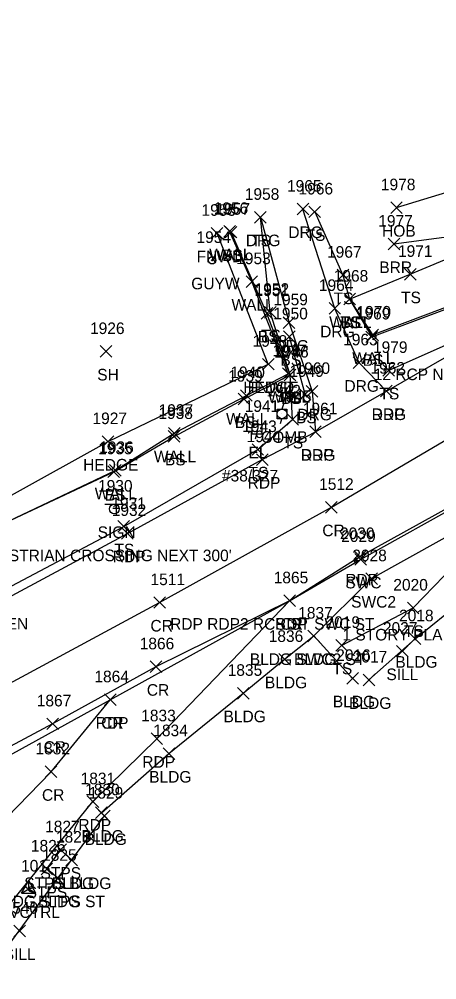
# Model space of a CAD drawing. Extents: x 1657482 to 1661439, y 647981 to 649041.
# Drawn here: x 1660007.4 to 1660079.4, y 648093.2 to 648258.8 of the extents above; entities that cross this region are included whole.
import ezdxf

# ---------------------------------------------------------------- set-up
doc = ezdxf.new("R2010")
doc.units = 0
for name, color, linetype in [('C_A', 7, 'Continuous'), ('C_I', 7, 'Continuous'), ('CPSM', 7, 'Continuous'), ('D_C', 7, 'Continuous'), ('L_A', 7, 'Continuous'), ('L_C', 7, 'Continuous'), ('L_I', 7, 'Continuous'), ('L_TIC', 7, 'Continuous'), ('LABL', 7, 'Continuous'), ('LAHR', 7, 'Continuous'), ('LBC', 7, 'Continuous'), ('LBF', 7, 'Continuous'), ('LELB', 7, 'Continuous'), ('LFNC', 7, 'Continuous'), ('LW', 7, 'Continuous'), ('P_A', 7, 'Continuous'), ('P_I', 7, 'Continuous'), ('P_TIC', 7, 'Continuous'), ('PET', 7, 'Continuous'), ('PRC', 7, 'Continuous'), ('R_A', 7, 'Continuous'), ('R_C', 7, 'Continuous'), ('R_I', 7, 'Continuous'), ('R_TIC', 7, 'Continuous'), ('RDG', 7, 'Continuous'), ('RSW', 7, 'Continuous'), ('S_A', 7, 'Continuous'), ('S_C', 7, 'Continuous'), ('S_I', 7, 'Continuous'), ('SSGN', 7, 'Continuous'), ('U_A', 7, 'Continuous'), ('U_C', 7, 'Continuous'), ('U_I', 7, 'Continuous'), ('UEPT', 7, 'Continuous'), ('UP', 7, 'Continuous'), ('UPGW', 7, 'Continuous')]:
    doc.layers.add(name, color=color, linetype=linetype)

msp = doc.modelspace()

# ---------------------------------------------------------------- linework, layer by layer
at = {"layer": 'CPSM'}
for p, q in [((1660007.81, 648108.16), (1660009.06, 648110.32)), ((1660007.81, 648108.16), (1660009.06, 648108.88)), ((1660010.31, 648108.16), (1660009.06, 648110.32)), ((1660009.06, 648108.88), (1660009.06, 648110.32)), ((1660009.06, 648108.88), (1660009.06, 648108.88)), ((1660009.06, 648108.88), (1660010.31, 648108.16)), ((1660007.81, 648108.16), (1660010.31, 648108.16))]:
    msp.add_line(p, q, dxfattribs=at)
at = {"layer": 'L_TIC'}
for points in [[(1660057.36, 648224.62), (1660059.36, 648226.62)], [(1660059.36, 648224.62), (1660057.36, 648226.62)], [(1660071.44, 648225.34), (1660073.44, 648227.34)], [(1660073.44, 648225.34), (1660071.44, 648227.34)], [(1660047.99, 648223.69), (1660049.99, 648225.69)], [(1660049.99, 648223.69), (1660047.99, 648225.69)], [(1660042.69, 648221.26), (1660044.69, 648223.26)], [(1660044.69, 648221.26), (1660042.69, 648223.26)], [(1660042.94, 648221.12), (1660044.94, 648223.12)], [(1660044.94, 648221.12), (1660042.94, 648223.12)], [(1660040.53, 648220.94), (1660042.53, 648222.94)], [(1660042.53, 648220.94), (1660040.53, 648222.94)], [(1660070.99, 648219.06), (1660072.99, 648221.06)], [(1660072.99, 648219.06), (1660070.99, 648221.06)], [(1660062.21, 648213.71), (1660064.21, 648215.71)], [(1660064.21, 648213.71), (1660062.21, 648215.71)], [(1660073.82, 648213.86), (1660075.82, 648215.86)], [(1660075.82, 648213.86), (1660073.82, 648215.86)], [(1660046.51, 648212.6), (1660048.51, 648214.6)], [(1660048.51, 648212.6), (1660046.51, 648214.6)], [(1660063.36, 648209.58), (1660065.36, 648211.58)], [(1660065.36, 648209.58), (1660063.36, 648211.58)], [(1660063.36, 648209.58), (1660065.36, 648211.58)], [(1660065.36, 648209.58), (1660063.36, 648211.58)], [(1660063.36, 648209.58), (1660065.36, 648211.58)], [(1660065.36, 648209.58), (1660063.36, 648211.58)], [(1660049.11, 648207.1), (1660051.11, 648209.1)], [(1660051.11, 648207.1), (1660049.11, 648209.1)], [(1660049.68, 648207.31), (1660051.68, 648209.31)], [(1660051.68, 648207.31), (1660049.68, 648209.31)], [(1660052.99, 648203.08), (1660054.99, 648205.08)], [(1660054.99, 648203.08), (1660052.99, 648205.08)], [(1660067.18, 648203.07), (1660069.18, 648205.07)], [(1660069.18, 648203.07), (1660067.18, 648205.07)], [(1660067.33, 648203.39), (1660069.33, 648205.39)], [(1660069.33, 648203.39), (1660067.33, 648205.39)], [(1660021.38, 648200.55), (1660023.38, 648202.55)], [(1660023.38, 648200.55), (1660021.38, 648202.55)], [(1660049.35, 648198.36), (1660051.35, 648200.36)], [(1660051.35, 648198.36), (1660049.35, 648200.36)], [(1660049.35, 648198.36), (1660051.35, 648200.36)], [(1660051.35, 648198.36), (1660049.35, 648200.36)], [(1660052.79, 648196.7), (1660054.79, 648198.7)], [(1660054.79, 648196.7), (1660052.79, 648198.7)], [(1660053.1, 648196.5), (1660055.1, 648198.5)], [(1660055.1, 648196.5), (1660053.1, 648198.5)], [(1660053.1, 648196.5), (1660055.1, 648198.5)], [(1660055.1, 648196.5), (1660053.1, 648198.5)], [(1660070.09, 648197.29), (1660072.09, 648199.29)], [(1660072.09, 648197.29), (1660070.09, 648199.29)], [(1660045.58, 648192.95), (1660047.58, 648194.95)], [(1660047.58, 648192.95), (1660045.58, 648194.95)], [(1660055.68, 648193.17), (1660057.68, 648195.17)], [(1660057.68, 648193.17), (1660055.68, 648195.17)], [(1660045.14, 648192.34), (1660047.14, 648194.34)], [(1660047.14, 648192.34), (1660045.14, 648194.34)], [(1660053.53, 648188.83), (1660055.53, 648190.83)], [(1660055.53, 648188.83), (1660053.53, 648190.83)], [(1660033.14, 648186.45), (1660035.14, 648188.45)], [(1660035.14, 648186.45), (1660033.14, 648188.45)], [(1660021.75, 648185.02), (1660023.75, 648187.02)], [(1660023.75, 648185.02), (1660021.75, 648187.02)], [(1660033.1, 648185.91), (1660035.1, 648187.91)], [(1660035.1, 648185.91), (1660033.1, 648187.91)], [(1660047.55, 648183.65), (1660049.55, 648185.65)], [(1660049.55, 648183.65), (1660047.55, 648185.65)], [(1660022.71, 648179.82), (1660024.71, 648181.82)], [(1660024.71, 648179.82), (1660022.71, 648181.82)], [(1660022.97, 648180.04), (1660024.97, 648182.04)], [(1660024.97, 648180.04), (1660022.97, 648182.04)], [(1660024.43, 648170.39), (1660026.43, 648172.39)], [(1660026.43, 648170.39), (1660024.43, 648172.39)], [(1660074.31, 648156.32), (1660076.31, 648158.32)], [(1660076.31, 648156.32), (1660074.31, 648158.32)], [(1660057.19, 648151.49), (1660059.19, 648153.49)], [(1660059.19, 648151.49), (1660057.19, 648153.49)], [(1660061.99, 648149.88), (1660063.99, 648151.88)], [(1660063.99, 648149.88), (1660061.99, 648151.88)], [(1660074.65, 648151.02), (1660076.65, 648153.02)], [(1660076.65, 648151.02), (1660074.65, 648153.02)], [(1660072.44, 648148.88), (1660074.44, 648150.88)], [(1660074.44, 648148.88), (1660072.44, 648150.88)], [(1660052.16, 648147.47), (1660054.16, 648149.47)], [(1660054.16, 648147.47), (1660052.16, 648149.47)], [(1660063.88, 648144.19), (1660065.88, 648146.19)], [(1660065.88, 648144.19), (1660063.88, 648146.19)], [(1660066.68, 648143.92), (1660068.68, 648145.92)], [(1660068.68, 648143.92), (1660066.68, 648145.92)], [(1660045.04, 648141.62), (1660047.04, 648143.62)], [(1660047.04, 648141.62), (1660045.04, 648143.62)], [(1660032.22, 648131.21), (1660034.22, 648133.21)], [(1660034.22, 648131.21), (1660032.22, 648133.21)], [(1660020.58, 648121.02), (1660022.58, 648123.02)], [(1660022.58, 648121.02), (1660020.58, 648123.02)], [(1660021.1, 648120.46), (1660023.1, 648122.46)], [(1660023.1, 648120.46), (1660021.1, 648122.46)], [(1660013.59, 648114.64), (1660015.59, 648116.64)], [(1660015.59, 648114.64), (1660013.59, 648116.64)], [(1660015.46, 648112.86), (1660017.46, 648114.86)], [(1660017.46, 648112.86), (1660015.46, 648114.86)], [(1660015.46, 648112.86), (1660017.46, 648114.86)], [(1660017.46, 648112.86), (1660015.46, 648114.86)], [(1660011.19, 648111.33), (1660013.19, 648113.33)], [(1660013.19, 648111.33), (1660011.19, 648113.33)], [(1660013.06, 648109.73), (1660015.06, 648111.73)], [(1660015.06, 648109.73), (1660013.06, 648111.73)], [(1660013.06, 648109.73), (1660015.06, 648111.73)], [(1660015.06, 648109.73), (1660013.06, 648111.73)], [(1660006.5, 648100.61), (1660008.5, 648102.61)], [(1660008.5, 648100.61), (1660006.5, 648102.61)]]:
    msp.add_lwpolyline(points, dxfattribs=at)
at = {"layer": 'LABL'}
msp.add_lwpolyline([(1660087.68, 648213.66), (1660086.68, 648222), (1660071.99, 648220.06)], dxfattribs=at)
at = {"layer": 'LAHR'}
msp.add_lwpolyline([(1659985.21, 648172.32), (1659989.36, 648167.49), (1660022.75, 648186.02), (1660050.35, 648199.36)], dxfattribs=at)
at = {"layer": 'LBC'}
for points in [[(1660072.44, 648226.34), (1660098.64, 648234.34)], [(1660067.68, 648144.92), (1660075.65, 648152.02), (1660086.44, 648160.72), (1660092.32, 648153.6)], [(1659994.61, 648056.01), (1659988.98, 648060.38), (1659986.84, 648067.33), (1659987.26, 648074.71), (1660003.37, 648096.28), (1660014.06, 648110.73), (1660016.46, 648113.86), (1660022.1, 648121.46), (1660021.58, 648122.02), (1660033.22, 648132.21), (1660046.04, 648142.62), (1660053.16, 648148.47), (1660058.19, 648152.49), (1660064.88, 648145.19)]]:
    msp.add_lwpolyline(points, dxfattribs=at)
at = {"layer": 'LBF'}
msp.add_lwpolyline([(1660014.06, 648110.73), (1660012.19, 648112.33), (1660014.59, 648115.64), (1660016.46, 648113.86)], dxfattribs=at)
at = {"layer": 'LELB'}
for points in [[(1660064.36, 648210.58), (1660068.18, 648204.07), (1660086, 648210.73), (1660103.81, 648220.76), (1660104.28, 648234.85)], [(1660071.09, 648198.29), (1660082.01, 648203.17), (1660097.37, 648212.32), (1660101.78, 648217.26), (1660103.81, 648220.76), (1660105.88, 648234.76)], [(1659996.18, 648158.98), (1659998.49, 648161.26), (1660000.72, 648162.37), (1660002.31, 648159.11), (1660025.43, 648171.39), (1660048.55, 648184.65), (1660054.53, 648189.83), (1660054.1, 648197.5), (1660050.68, 648208.31), (1660048.99, 648224.69)], [(1660058.36, 648225.62), (1660063.21, 648214.71), (1660064.36, 648210.58), (1660074.82, 648214.86), (1660083.46, 648218.52), (1660086.68, 648222)], [(1659986.23, 648162.85), (1659990.28, 648165.38), (1660003.1, 648171.11), (1660023.71, 648180.82), (1660034.1, 648186.91), (1660046.14, 648193.34), (1660054.1, 648197.5), (1660050.11, 648208.1), (1660043.94, 648222.12)], [(1660056.68, 648194.17), (1660053.99, 648204.08)], [(1660062.99, 648150.88), (1660075.31, 648157.32), (1660082.44, 648164.72), (1660087.74, 648165.94), (1660091.84, 648162.24), (1660098.33, 648160.41), (1660112.98, 648169), (1660137.25, 648180.59), (1660165.85, 648194.54)]]:
    msp.add_lwpolyline(points, dxfattribs=at)
at = {"layer": 'LFNC'}
msp.add_lwpolyline([(1660050.35, 648199.36), (1660041.53, 648221.94)], dxfattribs=at)
at = {"layer": 'LW'}
for points in [[(1660064.36, 648210.58), (1660068.33, 648204.39), (1660086.1, 648211.14), (1660103.48, 648220.81), (1660103.87, 648234.51)], [(1659986.33, 648163.5), (1659990.39, 648165.57), (1660003.32, 648171.23), (1660023.97, 648181.04), (1660034.14, 648187.45), (1660046.58, 648193.95), (1660053.79, 648197.7), (1660047.51, 648213.6), (1660043.69, 648222.26)]]:
    msp.add_lwpolyline(points, dxfattribs=at)
at = {"layer": 'P_TIC'}
for points in [[(1660069.69, 648193.72), (1660071.69, 648195.72)], [(1660071.69, 648193.72), (1660069.69, 648195.72)], [(1660057.48, 648186.71), (1660059.48, 648188.71)], [(1660059.48, 648186.71), (1660057.48, 648188.71)], [(1660048.31, 648181.91), (1660050.31, 648183.91)], [(1660050.31, 648181.91), (1660048.31, 648183.91)], [(1660060.23, 648173.69), (1660062.23, 648175.69)], [(1660062.23, 648173.69), (1660060.23, 648175.69)], [(1660025.06, 648169.19), (1660027.06, 648171.19)], [(1660027.06, 648169.19), (1660025.06, 648171.19)], [(1660065.13, 648165.2), (1660067.13, 648167.2)], [(1660067.13, 648165.2), (1660065.13, 648167.2)], [(1660030.61, 648157.26), (1660032.61, 648159.26)], [(1660032.61, 648157.26), (1660030.61, 648159.26)], [(1660053.02, 648157.57), (1660055.02, 648159.57)], [(1660055.02, 648157.57), (1660053.02, 648159.57)], [(1660053.02, 648157.57), (1660055.02, 648159.57)], [(1660055.02, 648157.57), (1660053.02, 648159.57)], [(1660053.02, 648157.57), (1660055.02, 648159.57)], [(1660055.02, 648157.57), (1660053.02, 648159.57)], [(1660029.99, 648146.19), (1660031.99, 648148.19)], [(1660031.99, 648146.19), (1660029.99, 648148.19)], [(1660022.12, 648140.51), (1660024.12, 648142.51)], [(1660024.12, 648140.51), (1660022.12, 648142.51)], [(1660022.12, 648140.51), (1660024.12, 648142.51)], [(1660024.12, 648140.51), (1660022.12, 648142.51)], [(1660012.19, 648136.35), (1660014.19, 648138.35)], [(1660014.19, 648136.35), (1660012.19, 648138.35)], [(1660030.14, 648133.78), (1660032.14, 648135.78)], [(1660032.14, 648133.78), (1660030.14, 648135.78)], [(1660011.91, 648128.08), (1660013.91, 648130.08)], [(1660013.91, 648128.08), (1660011.91, 648130.08)], [(1660019.13, 648122.93), (1660021.13, 648124.93)], [(1660021.13, 648122.93), (1660019.13, 648124.93)]]:
    msp.add_lwpolyline(points, dxfattribs=at)
at = {"layer": 'PET'}
for points in [[(1660001.58, 648157.02), (1660026.06, 648170.19), (1660049.31, 648182.91), (1660058.48, 648187.71), (1660070.69, 648194.72), (1660099.22, 648211.06), (1660115.83, 648220.6), (1660127.5, 648227.39), (1660147.04, 648238.71), (1660181.49, 648258.83)], [(1660002.92, 648130.4), (1660023.12, 648141.51), (1660054.02, 648158.57), (1660066.13, 648166.2), (1660084.52, 648176.38), (1660103.19, 648187.33), (1660126.13, 648200.1), (1660157.8, 648218.16), (1660193.82, 648238.55)], [(1659998.69, 648097.5), (1660020.13, 648123.93), (1660031.14, 648134.78), (1660054.02, 648158.57)]]:
    msp.add_lwpolyline(points, dxfattribs=at)
at = {"layer": 'PRC'}
for points in [[(1659666.14, 648110.53), (1659699.55, 648107.38), (1659729.53, 648104.33), (1659765.5, 648101.14), (1659792.99, 648098.38), (1659818.73, 648097.21), (1659849.22, 648095.84), (1659870.33, 648096.36), (1659894.6, 648099.46), (1659913.11, 648103.66), (1659935.29, 648110.79), (1659956.94, 648119.93), (1659978.86, 648130.6), (1660002.08, 648142.33), (1660031.61, 648158.26), (1660061.23, 648174.69), (1660097.08, 648195.77), (1660113.88, 648205.48), (1660151.73, 648227.3), (1660188.69, 648248.66)], [(1660054.02, 648158.57), (1660030.99, 648147.19), (1660013.19, 648137.35), (1659987.25, 648123.49)], [(1659963.46, 648069.89), (1659971.31, 648084.48), (1659988.17, 648103.59), (1660012.91, 648129.08), (1660023.12, 648141.51)]]:
    msp.add_lwpolyline(points, dxfattribs=at)
at = {"layer": 'R_TIC'}
for points in [[(1660055.31, 648225.1), (1660057.31, 648227.1)], [(1660057.31, 648225.1), (1660055.31, 648227.1)], [(1660047.99, 648223.69), (1660049.99, 648225.69)], [(1660049.99, 648223.69), (1660047.99, 648225.69)], [(1660060.81, 648207.98), (1660062.81, 648209.98)], [(1660062.81, 648207.98), (1660060.81, 648209.98)], [(1660052.92, 648205.51), (1660054.92, 648207.51)], [(1660054.92, 648205.51), (1660052.92, 648207.51)], [(1660064.99, 648198.6), (1660066.99, 648200.6)], [(1660066.99, 648198.6), (1660064.99, 648200.6)], [(1660056.88, 648193.67), (1660058.88, 648195.67)], [(1660058.88, 648193.67), (1660056.88, 648195.67)], [(1660069.69, 648193.72), (1660071.69, 648195.72)], [(1660071.69, 648193.72), (1660069.69, 648195.72)], [(1660057.48, 648186.71), (1660059.48, 648188.71)], [(1660059.48, 648186.71), (1660057.48, 648188.71)], [(1660065.26, 648164.7), (1660067.26, 648166.7)], [(1660067.26, 648164.7), (1660065.26, 648166.7)], [(1660067.16, 648161.38), (1660069.16, 648163.38)], [(1660069.16, 648161.38), (1660067.16, 648163.38)], [(1660053.02, 648157.57), (1660055.02, 648159.57)], [(1660055.02, 648157.57), (1660053.02, 648159.57)], [(1660057.19, 648151.49), (1660059.19, 648153.49)], [(1660059.19, 648151.49), (1660057.19, 648153.49)]]:
    msp.add_lwpolyline(points, dxfattribs=at)
at = {"layer": 'RDG'}
for points in [[(1660048.99, 648224.69), (1660053.92, 648206.51), (1660057.88, 648194.67), (1660058.48, 648187.71)], [(1660070.69, 648194.72), (1660065.99, 648199.6), (1660061.81, 648208.98), (1660056.31, 648226.1)]]:
    msp.add_lwpolyline(points, dxfattribs=at)
at = {"layer": 'RSW'}
for points in [[(1660054.02, 648158.57), (1660066.26, 648165.7), (1660084.78, 648176.02), (1660103.25, 648187.06), (1660126.27, 648199.92), (1660157.8, 648218.16)], [(1660058.19, 648152.49), (1660068.16, 648162.38), (1660086.38, 648172.58), (1660091.77, 648175.55), (1660105.15, 648183.47), (1660128.23, 648196.61), (1660156.81, 648212.92), (1660160.17, 648214.59)]]:
    msp.add_lwpolyline(points, dxfattribs=at)
at = {"layer": 'SSGN'}
for p, q in [((1660022.16, 648175.24), (1660025.49, 648175.24)), ((1660023.81, 648174.4), (1660023.81, 648174.4))]:
    msp.add_line(p, q, dxfattribs=at)
msp.add_circle((1660023.81, 648174.4), 0.833, dxfattribs=at)
at = {"layer": 'UEPT'}
for p, q in [((1660047.57, 648187.3), (1660047.57, 648188.97)), ((1660047.57, 648188.97), (1660049.24, 648188.97)), ((1660048.57, 648189.8), (1660048.4, 648188.97)), ((1660049.24, 648188.97), (1660049.24, 648187.3)), ((1660049.24, 648187.3), (1660047.57, 648187.3)), ((1660048.15, 648186.47), (1660048.4, 648187.3)), ((1660048.4, 648188.13), (1660048.4, 648188.13))]:
    msp.add_line(p, q, dxfattribs=at)
at = {"layer": 'UP'}
for p, q in [((1660051.87, 648189.95), (1660051.87, 648191.62)), ((1660051.87, 648191.62), (1660053.53, 648191.62)), ((1660052.95, 648192.45), (1660052.7, 648191.62)), ((1660053.53, 648191.62), (1660053.53, 648189.95)), ((1660053.53, 648189.95), (1660051.87, 648189.95)), ((1660052.45, 648189.12), (1660052.7, 648189.95)), ((1660052.7, 648190.79), (1660052.7, 648190.79))]:
    msp.add_line(p, q, dxfattribs=at)
msp.add_circle((1660052.7, 648190.79), 0.833, dxfattribs=at)
at = {"layer": 'UPGW'}
for radius in [0.625, 0.0833]:
    msp.add_circle((1660040.67, 648217.26), radius, dxfattribs=at)

# ---------------------------------------------------------------- texts
at = {"layer": 'C_A'}
msp.add_text('HVCTRL', height=2, dxfattribs=at).set_placement((1660003.75, 648103.88))
at = {"layer": 'C_I'}
msp.add_text('101', height=2, dxfattribs=at).set_placement((1660007.75, 648111.88))
at = {"layer": 'D_C'}
msp.add_text('12 RCP NO OTHER PIPES VISIBLE', height=2, dxfattribs=at).set_placement((1660068.52, 648196.6))
at = {"layer": 'L_A'}
for s, p in [('HOB', (1660069.95, 648221.34)), ('TS', (1660047.4, 648219.69)), ('TS', (1660056.77, 648220.62)), ('FNWD', (1660038, 648216.94)), ('WALL', (1660040.17, 648217.26)), ('BS', (1660042.38, 648217.12)), ('BRR', (1660069.48, 648215.06)), ('TS', (1660061.62, 648209.71)), ('TS', (1660073.23, 648209.86)), ('WALL', (1660044, 648208.6)), ('WALL', (1660060.85, 648205.58)), ('TS', (1660062.77, 648205.58)), ('BS', (1660062.8, 648205.58)), ('BS', (1660048.55, 648203.1)), ('TS', (1660049.09, 648203.31)), ('BS', (1660052.43, 648199.08)), ('WALL', (1660064.81, 648199.39)), ('BS', (1660066.62, 648199.07)), ('SH', (1660020.87, 648196.55)), ('HEDGE', (1660046.05, 648194.36)), ('FNWD', (1660046.81, 648194.36)), ('TS', (1660069.5, 648193.29)), ('WALL', (1660050.27, 648192.7)), ('TS', (1660052.51, 648192.5)), ('BS', (1660052.54, 648192.5)), ('WALL', (1660043.07, 648188.95)), ('BS', (1660044.59, 648188.34)), ('BS', (1660055.12, 648189.17)), ('TS', (1660052.94, 648184.83)), ('WALL', (1660030.63, 648182.45)), ('BS', (1660032.54, 648181.91)), ('HEDGE', (1660018.45, 648181.02)), ('TS', (1660046.96, 648179.65)), ('WALL', (1660020.45, 648176.04)), ('BS', (1660022.15, 648175.82)), ('TS', (1660023.84, 648166.39)), ('TS', (1660073.72, 648152.32)), ('BLDG', (1660054.78, 648147.49)), ('BLDG', (1660072.24, 648147.02)), ('TS', (1660061.4, 648145.88)), ('SILL', (1660070.7, 648144.88)), ('BLDG', (1660049.76, 648143.47)), ('BLDG', (1660061.47, 648140.19)), ('BLDG', (1660064.27, 648139.92)), ('BLDG', (1660042.63, 648137.62)), ('BLDG', (1660029.82, 648127.21)), ('BLDG', (1660018.17, 648117.02)), ('BLDG', (1660018.69, 648116.46)), ('STPS', (1660011.11, 648110.64)), ('STPS BLDG', (1660008.29, 648108.86)), ('BLDG', (1660013.05, 648108.86)), ('STPS', (1660008.71, 648107.33)), ('BLDG STPS ST', (1660003.03, 648105.73)), ('BLDG', (1660010.65, 648105.73)), ('SILL', (1660004.76, 648096.61))]:
    msp.add_text(s, height=2, dxfattribs=at).set_placement(p)
at = {"layer": 'L_C'}
msp.add_text('1 STORY PLAINFIELD HISTORICAL', height=2, dxfattribs=at).set_placement((1660063.12, 648151.72))
at = {"layer": 'L_I'}
for s, p in [('1978', (1660069.75, 648229.34)), ('1958', (1660046.3, 648227.69)), ('1966', (1660055.56, 648228.62)), ('1955', (1660038.84, 648224.94)), ('1956', (1660040.94, 648225.26)), ('1957', (1660041.24, 648225.12)), ('1977', (1660069.3, 648223.06)), ('1967', (1660060.47, 648217.71)), ('1971', (1660072.7, 648217.86)), ('1953', (1660044.82, 648216.6)), ('1968', (1660061.62, 648213.58)), ('1968', (1660061.62, 648213.58)), ('1968', (1660061.62, 648213.58)), ('1952', (1660047.99, 648211.31)), ('1951', (1660047.99, 648211.1)), ('1950', (1660051.21, 648207.08)), ('1969', (1660065.43, 648207.07)), ('1970', (1660065.55, 648207.39)), ('1926', (1660019.63, 648204.55)), ('1948', (1660047.65, 648202.36)), ('1948', (1660047.65, 648202.36)), ('1979', (1660068.39, 648201.29)), ('1947', (1660051.09, 648200.7)), ('1946', (1660051.35, 648200.5)), ('1946', (1660051.35, 648200.5)), ('1939', (1660043.44, 648196.34)), ('1940', (1660043.81, 648196.95)), ('1949', (1660053.98, 648197.17)), ('1945', (1660051.84, 648192.83)), ('1938', (1660031.41, 648189.91)), ('1937', (1660031.45, 648190.45)), ('1927', (1660020.05, 648189.02)), ('1943', (1660045.86, 648187.65)), ('1935', (1660021.02, 648183.82)), ('1936', (1660021.22, 648184.04)), ('1931', (1660023.3, 648174.39)), ('2020', (1660071.89, 648160.32)), ('1837', (1660055.5, 648155.49)), ('2018', (1660072.88, 648155.02)), ('2019', (1660060.21, 648153.88)), ('1836', (1660050.42, 648151.47)), ('2027', (1660070.1, 648152.88)), ('2016', (1660062.05, 648148.19)), ('2017', (1660064.9, 648147.92)), ('1835', (1660043.35, 648145.62)), ('1834', (1660030.53, 648135.21)), ('1830', (1660018.8, 648125.02)), ('1829', (1660019.4, 648124.46)), ('1827', (1660011.89, 648118.64)), ('1828', (1660013.76, 648116.86)), ('1828', (1660013.76, 648116.86)), ('1826', (1660009.44, 648115.33)), ('1825', (1660011.37, 648113.73)), ('1825', (1660011.37, 648113.73)), ('1540', (1660004.73, 648104.61))]:
    msp.add_text(s, height=2, dxfattribs=at).set_placement(p)
at = {"layer": 'P_A'}
for s, p in [('RDP', (1660068.17, 648189.72)), ('RDP', (1660055.96, 648182.71)), ('RDP', (1660046.79, 648177.91)), ('CR', (1660059.66, 648169.69)), ('RDP', (1660023.55, 648165.19)), ('RDP', (1660063.61, 648161.2)), ('CR', (1660030.04, 648153.26)), ('RDP', (1660051.51, 648153.57)), ('RDP', (1660051.51, 648153.57)), ('CR', (1660052.45, 648153.57)), ('CR', (1660029.42, 648142.19)), ('RDP', (1660020.61, 648136.51)), ('CR', (1660021.55, 648136.51)), ('CR', (1660011.63, 648132.35)), ('RDP', (1660028.63, 648129.78)), ('CR', (1660011.35, 648124.08)), ('RDP', (1660017.62, 648118.93))]:
    msp.add_text(s, height=2, dxfattribs=at).set_placement(p)
at = {"layer": 'P_I'}
for s, p in [('1962', (1660067.95, 648197.72)), ('1961', (1660056.3, 648190.71)), ('1944', (1660046.61, 648185.91)), ('1512', (1660059.11, 648177.69)), ('1932', (1660023.37, 648173.19)), ('2030', (1660062.7, 648169.2)), ('1865', (1660051.28, 648161.57)), ('1865', (1660051.28, 648161.57)), ('1865', (1660051.28, 648161.57)), ('1511', (1660030.05, 648161.26)), ('1866', (1660028.19, 648150.19)), ('1864', (1660020.38, 648144.51)), ('1864', (1660020.38, 648144.51)), ('1867', (1660010.45, 648140.35)), ('1833', (1660028.45, 648137.78)), ('1832', (1660010.22, 648132.08)), ('1831', (1660018.01, 648126.93))]:
    msp.add_text(s, height=2, dxfattribs=at).set_placement(p)
at = {"layer": 'R_A'}
for s, p in [('DRG', (1660053.8, 648221.1)), ('DRG', (1660046.48, 648219.69)), ('DRG', (1660059.29, 648203.98)), ('DRG', (1660051.41, 648201.51)), ('DRG', (1660063.47, 648194.6)), ('DRG', (1660055.37, 648189.67)), ('DRG', (1660068.17, 648189.72)), ('DRG', (1660055.96, 648182.71)), ('SWC', (1660063.62, 648160.7)), ('SWC2', (1660064.63, 648157.38)), ('RDP RDP2 RCS ST SWC ST', (1660033.43, 648153.57)), ('BLDG SWC2 ST', (1660047.16, 648147.49))]:
    msp.add_text(s, height=2, dxfattribs=at).set_placement(p)
at = {"layer": 'R_C'}
msp.add_text('WOODEN', height=2, dxfattribs=at).set_placement((1659996.63, 648153.61))
at = {"layer": 'R_I'}
for s, p in [('1958', (1660046.3, 648227.69)), ('1965', (1660053.57, 648229.1)), ('1964', (1660059.07, 648211.98)), ('1959', (1660051.22, 648209.51)), ('1963', (1660063.25, 648202.6)), ('1960', (1660055.05, 648197.67)), ('1962', (1660067.95, 648197.72)), ('1961', (1660056.3, 648190.71)), ('2029', (1660062.91, 648168.7)), ('2028', (1660064.82, 648165.38)), ('1865', (1660051.28, 648161.57)), ('1837', (1660055.5, 648155.49))]:
    msp.add_text(s, height=2, dxfattribs=at).set_placement(p)
at = {"layer": 'S_A'}
msp.add_text('SIGN', height=2, dxfattribs=at).set_placement((1660020.94, 648169.38))
at = {"layer": 'S_C'}
msp.add_text("PEDESTRIAN CROSSING NEXT 300'", height=2, dxfattribs=at).set_placement((1659998.35, 648165.38))
at = {"layer": 'S_I'}
msp.add_text('1930', height=2, dxfattribs=at).set_placement((1660021.01, 648177.38))
at = {"layer": 'U_A'}
for s, p in [('GUYW', (1660037.07, 648212.26)), ('COMB', (1660049.09, 648185.79)), ('EL', (1660046.94, 648183.13))]:
    msp.add_text(s, height=2, dxfattribs=at).set_placement(p)
at = {"layer": 'U_C'}
msp.add_text('#38/327', height=2, dxfattribs=at).set_placement((1660042.37, 648179.13))
at = {"layer": 'U_I'}
for s, p in [('1954', (1660037.98, 648220.26)), ('1942', (1660050.01, 648193.79)), ('1941', (1660046.28, 648191.13))]:
    msp.add_text(s, height=2, dxfattribs=at).set_placement(p)

doc.saveas('drawing.dxf')
